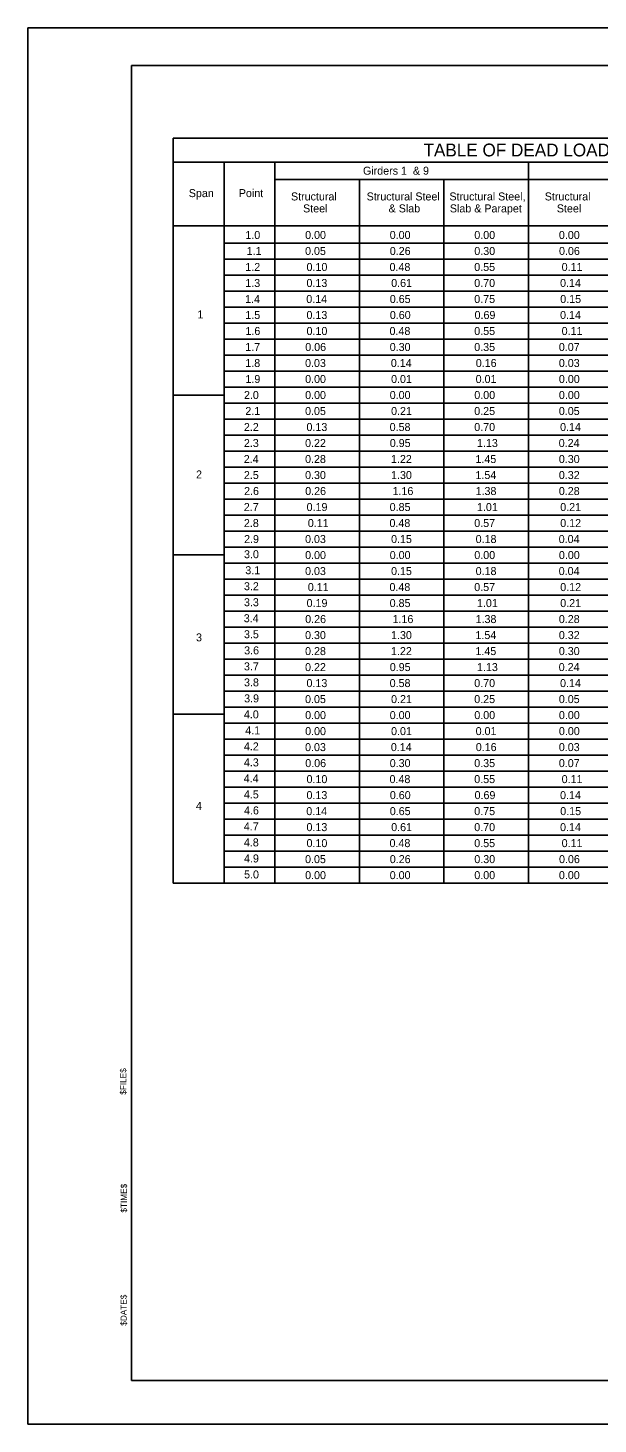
# Model space of a CAD drawing. Extents: x 208.7 to 242.8, y 328.9 to 350.7.
# Drawn here: x 208.66 to 217.57, y 328.91 to 350.71 of the extents above; entities that cross this region are included whole.
import ezdxf

# ---------------------------------------------------------------- set-up
doc = ezdxf.new("R2010")
doc.units = 0
for name, color, linetype in [('border', 7, 'Continuous'), ('Border 2660-Hwy18 - Level 62', 7, 'Continuous'), ('Steel', 7, 'Continuous'), ('Text', 7, 'Continuous'), ('Title Text', 7, 'Continuous')]:
    doc.layers.add(name, color=color, linetype=linetype)

msp = doc.modelspace()

# ---------------------------------------------------------------- linework, layer by layer
at = {"layer": 'border'}
for p, q in [((210.28, 350.129), (242.291, 350.129)), ((210.28, 329.584), (210.28, 350.129)), ((242.291, 329.584), (210.28, 329.584))]:
    msp.add_line(p, q, dxfattribs=at)
at = {"layer": 'Border 2660-Hwy18 - Level 62'}
msp.add_lwpolyline([(208.659, 350.715), (242.778, 350.715), (242.778, 328.905), (208.659, 328.905)], close=True, dxfattribs=at)
at = {"layer": 'Steel'}
for p, q in [((210.932, 348.995), (210.932, 337.354)), ((224.415, 348.995), (210.932, 348.995)), ((224.415, 348.618), (210.932, 348.618)), ((211.725, 348.618), (211.725, 337.354)), ((212.517, 348.618), (212.517, 337.354)), ((216.483, 348.618), (216.483, 337.354)), ((224.415, 348.349), (212.517, 348.349)), ((213.839, 348.349), (213.839, 337.354)), ((215.161, 348.349), (215.161, 337.354)), ((224.415, 347.623), (210.932, 347.623)), ((224.415, 347.354), (211.725, 347.354)), ((224.415, 347.104), (211.725, 347.104)), ((224.415, 346.854), (211.725, 346.854)), ((224.415, 346.604), (211.725, 346.604)), ((224.415, 346.354), (211.725, 346.354)), ((224.415, 346.104), (211.725, 346.104)), ((224.415, 345.854), (211.725, 345.854)), ((224.415, 345.604), (211.725, 345.604)), ((224.415, 345.354), (211.725, 345.354)), ((224.415, 345.104), (211.725, 345.104)), ((211.725, 344.976), (210.932, 344.976)), ((224.415, 344.854), (211.725, 344.854)), ((224.415, 344.604), (211.725, 344.604)), ((224.415, 344.354), (211.725, 344.354)), ((224.415, 344.104), (211.725, 344.104)), ((224.415, 343.854), (211.725, 343.854)), ((224.415, 343.604), (211.725, 343.604)), ((224.415, 343.354), (211.725, 343.354)), ((224.415, 343.104), (211.725, 343.104)), ((224.415, 342.854), (211.725, 342.854)), ((211.725, 342.486), (210.932, 342.486)), ((224.415, 342.604), (211.725, 342.604)), ((224.415, 342.354), (211.725, 342.354)), ((224.415, 342.104), (211.725, 342.104)), ((224.415, 341.854), (211.725, 341.854)), ((224.415, 341.604), (211.725, 341.604)), ((224.415, 341.354), (211.725, 341.354)), ((224.415, 341.104), (211.725, 341.104)), ((224.415, 340.854), (211.725, 340.854)), ((224.415, 340.604), (211.725, 340.604)), ((224.415, 340.354), (211.725, 340.354)), ((224.415, 340.104), (211.725, 340.104)), ((211.725, 339.996), (210.932, 339.996)), ((224.415, 339.854), (211.725, 339.854)), ((224.415, 339.604), (211.725, 339.604)), ((224.415, 339.354), (211.725, 339.354)), ((224.415, 339.104), (211.725, 339.104)), ((224.415, 338.854), (211.725, 338.854)), ((224.415, 338.604), (211.725, 338.604)), ((224.415, 338.354), (211.725, 338.354)), ((224.415, 338.104), (211.725, 338.104)), ((224.415, 337.854), (211.725, 337.854)), ((224.415, 337.604), (211.725, 337.604)), ((224.415, 337.354), (210.932, 337.354))]:
    msp.add_line(p, q, dxfattribs=at)

# ---------------------------------------------------------------- texts
at = {"layer": 'border'}
for s, p in [('$FILE$', (210.197, 334.05)), ('$TIME$', (210.206, 332.209)), ('$DATE$', (210.203, 330.442))]:
    msp.add_text(s, height=0.096, rotation=89.9999, dxfattribs=at).set_placement(p)
at = {"layer": 'Text'}
for s, p in [('Girders 1  & 9', (213.896, 348.422)), ('Span', (211.174, 348.072)), ('Point', (211.956, 348.072)), ('Structural', (212.771, 348.02)), ('Structural Steel', (213.953, 348.02)), ('Structural Steel,', (215.247, 348.02)), ('Structural', (216.737, 348.02)), ('Steel', (212.96, 347.833)), ('& Slab', (214.297, 347.833)), ('Slab & Parapet', (215.254, 347.833)), ('Steel', (216.926, 347.833)), ('1.0', (212.058, 347.418)), ('0.00', (212.992, 347.418)), ('0.00', (214.314, 347.418)), ('0.00', (215.636, 347.418)), ('0.00', (216.958, 347.418)), ('1.1', (212.078, 347.168)), ('0.05', (212.991, 347.168)), ('0.26', (214.315, 347.168)), ('0.30', (215.636, 347.168)), ('0.06', (216.96, 347.168)), ('1.2', (212.057, 346.918)), ('0.10', (213.014, 346.918)), ('0.48', (214.311, 346.918)), ('0.55', (215.635, 346.918)), ('0.11', (217.001, 346.918)), ('1.3', (212.057, 346.668)), ('0.13', (213.013, 346.668)), ('0.61', (214.337, 346.668)), ('0.70', (215.635, 346.668)), ('0.14', (216.976, 346.668)), ('1.4', (212.054, 346.418)), ('0.14', (213.01, 346.418)), ('0.65', (214.315, 346.418)), ('0.75', (215.635, 346.418)), ('0.15', (216.979, 346.418)), ('1', (211.309, 346.177)), ('1.5', (212.057, 346.168)), ('0.13', (213.013, 346.168)), ('0.60', (214.316, 346.168)), ('0.69', (215.64, 346.168)), ('0.14', (216.976, 346.168)), ('1.6', (212.059, 345.918)), ('0.10', (213.014, 345.918)), ('0.48', (214.311, 345.918)), ('0.55', (215.635, 345.918)), ('0.11', (217.001, 345.918)), ('1.7', (212.056, 345.668)), ('0.06', (212.994, 345.668)), ('0.30', (214.314, 345.668)), ('0.35', (215.635, 345.668)), ('0.07', (216.957, 345.668)), ('1.8', (212.057, 345.418)), ('0.03', (212.991, 345.418)), ('0.14', (214.332, 345.418)), ('0.16', (215.659, 345.418)), ('0.03', (216.957, 345.418)), ('1.9', (212.059, 345.168)), ('0.00', (212.992, 345.168)), ('0.01', (214.335, 345.168)), ('0.01', (215.657, 345.168)), ('0.00', (216.958, 345.168)), ('2.0', (212.036, 344.918)), ('0.00', (212.992, 344.918)), ('0.00', (214.314, 344.918)), ('0.00', (215.636, 344.918)), ('0.00', (216.958, 344.918)), ('2.1', (212.057, 344.668)), ('0.05', (212.991, 344.668)), ('0.21', (214.335, 344.668)), ('0.25', (215.635, 344.668)), ('0.05', (216.957, 344.668)), ('2.2', (212.035, 344.418)), ('0.13', (213.013, 344.418)), ('0.58', (214.313, 344.418)), ('0.70', (215.635, 344.418)), ('0.14', (216.976, 344.418)), ('2.3', (212.035, 344.168)), ('0.22', (212.991, 344.168)), ('0.95', (214.315, 344.168)), ('1.13', (215.678, 344.168)), ('0.24', (216.955, 344.168)), ('2.4', (212.033, 343.918)), ('0.28', (212.991, 343.918)), ('1.22', (214.334, 343.918)), ('1.45', (215.654, 343.918)), ('0.30', (216.957, 343.918)), ('2', (211.287, 343.677)), ('2.5', (212.035, 343.668)), ('0.30', (212.991, 343.668)), ('1.30', (214.335, 343.668)), ('1.54', (215.654, 343.668)), ('0.32', (216.957, 343.668)), ('2.6', (212.038, 343.418)), ('0.26', (212.993, 343.418)), ('1.16', (214.358, 343.418)), ('1.38', (215.656, 343.418)), ('0.28', (216.957, 343.418)), ('2.7', (212.034, 343.168)), ('0.19', (213.015, 343.168)), ('0.85', (214.313, 343.168)), ('1.01', (215.678, 343.168)), ('0.21', (216.979, 343.168)), ('2.8', (212.035, 342.918)), ('0.11', (213.034, 342.918)), ('0.48', (214.31, 342.918)), ('0.57', (215.635, 342.918)), ('0.12', (216.979, 342.918)), ('2.9', (212.038, 342.668)), ('0.03', (212.991, 342.668)), ('0.15', (214.335, 342.668)), ('0.18', (215.657, 342.668)), ('0.04', (216.955, 342.668)), ('3.0', (212.037, 342.431)), ('0.00', (212.992, 342.418)), ('0.00', (214.314, 342.418)), ('0.00', (215.636, 342.418)), ('0.00', (216.958, 342.418)), ('3.1', (212.057, 342.181)), ('0.03', (212.991, 342.168)), ('0.15', (214.335, 342.168)), ('0.18', (215.657, 342.168)), ('0.04', (216.955, 342.168)), ('3.2', (212.036, 341.931)), ('0.11', (213.034, 341.918)), ('0.48', (214.31, 341.918)), ('0.57', (215.635, 341.918)), ('0.12', (216.979, 341.918)), ('3.3', (212.036, 341.681)), ('0.19', (213.015, 341.668)), ('0.85', (214.313, 341.668)), ('1.01', (215.678, 341.668)), ('0.21', (216.979, 341.668)), ('3.4', (212.033, 341.431)), ('0.26', (212.993, 341.418)), ('1.16', (214.358, 341.418)), ('1.38', (215.656, 341.418)), ('0.28', (216.957, 341.418)), ('3', (211.287, 341.132)), ('3.5', (212.036, 341.181)), ('0.30', (212.991, 341.168)), ('1.30', (214.335, 341.168)), ('1.54', (215.654, 341.168)), ('0.32', (216.957, 341.168)), ('3.6', (212.039, 340.929)), ('0.28', (212.991, 340.918)), ('1.22', (214.334, 340.918)), ('1.45', (215.654, 340.918)), ('0.30', (216.957, 340.918)), ('3.7', (212.036, 340.679)), ('0.22', (212.991, 340.668)), ('0.95', (214.315, 340.668)), ('1.13', (215.678, 340.668)), ('0.24', (216.955, 340.668)), ('3.8', (212.037, 340.429)), ('0.13', (213.013, 340.418)), ('0.58', (214.313, 340.418)), ('0.70', (215.635, 340.418)), ('0.14', (216.976, 340.418)), ('3.9', (212.039, 340.179)), ('0.05', (212.991, 340.168)), ('0.21', (214.335, 340.168)), ('0.25', (215.635, 340.168)), ('0.05', (216.957, 340.168)), ('4.0', (212.035, 339.929)), ('0.00', (212.992, 339.918)), ('0.00', (214.314, 339.918)), ('0.00', (215.636, 339.918)), ('0.00', (216.958, 339.918)), ('4.1', (212.056, 339.679)), ('0.00', (212.992, 339.668)), ('0.01', (214.335, 339.668)), ('0.01', (215.657, 339.668)), ('0.00', (216.958, 339.668)), ('4.2', (212.035, 339.429)), ('0.03', (212.991, 339.418)), ('0.14', (214.332, 339.418)), ('0.16', (215.659, 339.418)), ('0.03', (216.957, 339.418)), ('4.3', (212.035, 339.179)), ('0.06', (212.994, 339.168)), ('0.30', (214.314, 339.168)), ('0.35', (215.635, 339.168)), ('0.07', (216.957, 339.168)), ('4.4', (212.032, 338.929)), ('0.10', (213.014, 338.918)), ('0.48', (214.311, 338.918)), ('0.55', (215.635, 338.918)), ('0.11', (217.001, 338.918)), ('4.5', (212.035, 338.679)), ('0.13', (213.013, 338.668)), ('0.60', (214.316, 338.668)), ('0.69', (215.64, 338.668)), ('0.14', (216.976, 338.668)), ('4', (211.285, 338.5)), ('4.6', (212.037, 338.429)), ('0.14', (213.01, 338.418)), ('0.65', (214.315, 338.418)), ('0.75', (215.635, 338.418)), ('0.15', (216.979, 338.418)), ('4.7', (212.034, 338.179)), ('0.13', (213.013, 338.168)), ('0.61', (214.337, 338.168)), ('0.70', (215.635, 338.168)), ('0.14', (216.976, 338.168)), ('4.8', (212.035, 337.929)), ('0.10', (213.014, 337.918)), ('0.48', (214.311, 337.918)), ('0.55', (215.635, 337.918)), ('0.11', (217.001, 337.918)), ('4.9', (212.037, 337.679)), ('0.05', (212.991, 337.668)), ('0.26', (214.315, 337.668)), ('0.30', (215.636, 337.668)), ('0.06', (216.96, 337.668)), ('5.0', (212.038, 337.429)), ('0.00', (212.992, 337.418)), ('0.00', (214.314, 337.418)), ('0.00', (215.636, 337.418)), ('0.00', (216.958, 337.418))]:
    msp.add_text(s, height=0.125, dxfattribs=at).set_placement(p)
at = {"layer": 'Title Text'}
msp.add_text('TABLE OF DEAD LOAD DEFLECTIONS (INCHES)', height=0.2, dxfattribs=at).set_placement((214.842, 348.708))

doc.saveas('drawing.dxf')
